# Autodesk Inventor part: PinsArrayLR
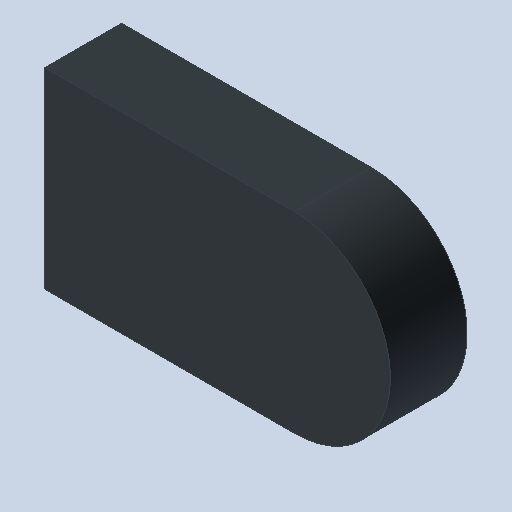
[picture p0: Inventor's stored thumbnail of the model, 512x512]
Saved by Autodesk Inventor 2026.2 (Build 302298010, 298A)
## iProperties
Created: 2026-10
Part Number: PinsArrayLR
Material: Générique
Document SubType Name: Modeling
Designer: mel
Density: 1 g/cm^3
Appearance: Par défaut
Author: mel
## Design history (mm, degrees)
feature "Base1"
node "Solide1"
